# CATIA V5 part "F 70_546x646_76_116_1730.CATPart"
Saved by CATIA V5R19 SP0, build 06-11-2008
Definition: F 70_546x646_76_116_1730
Nomenclature: F 70_546x646_76_116_1730
Description: PART--DESC
Material "Steel": density 7860 kg/m3, Young's modulus 2e+11 Pa, Poisson ratio 0.266, thermal expansion 1.17e-05 1/K
Bounding box of the stored display mesh (mm): x -323 to 323, y -273 to 273, z -278 to -162
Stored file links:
  G:\UTB\Kombinované\Bakalářská práce\Catia\FORMA\F 70_546x646_76_116_1730.CATPart
  D:\Aplikace\CATIA\Nová složka\win_b64\startup\materials\Catalog.CATMaterial
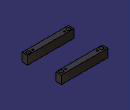
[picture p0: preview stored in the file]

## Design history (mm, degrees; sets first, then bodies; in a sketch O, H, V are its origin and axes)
Body1 "F 70_546646_76_116_1730" (main body)
  Solid1: solid without history
Body2 "F 70_546646_76_116_1730"
  Solid2: solid without history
